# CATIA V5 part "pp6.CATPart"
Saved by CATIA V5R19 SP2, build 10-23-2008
Part number: pp6
Publications: "Line.1", "Point.3", "Plane.2", "Line.2", "Point.4"
Bounding box of the stored display mesh (mm): x 0 to 20, y 0 to 100, z 0 to 50
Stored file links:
  C:\Users\Welcome\Documents\thinkm2\pp6.CATPart
  C:\Users\Welcome\Documents\thinkm2\Brasmeca.CATProduct
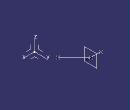
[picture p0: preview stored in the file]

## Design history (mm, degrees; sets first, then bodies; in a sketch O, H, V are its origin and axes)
AxisSystem1: origin (0, 0, 0), X (1, 0, 0), Y (0, 1, 0), Z (0, 0, 1)
Set1
  Point1: linked copy from another document
Body1 (main body)
  Line1: type PtDir, RefPoint Point1, Direction edge [XY plane of AxisSystem1 | ZX plane of AxisSystem1], Start 0, End 20
  Point2: type OnCurve, Support Line1, Length 15
  Plane1: type Normal, Curve Line1, RefPoint Point2
  Point3: (15, 50, 25), in AxisSystem1
  Line2: type PtPt, FirstPoint Point2, SecondPoint Point3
